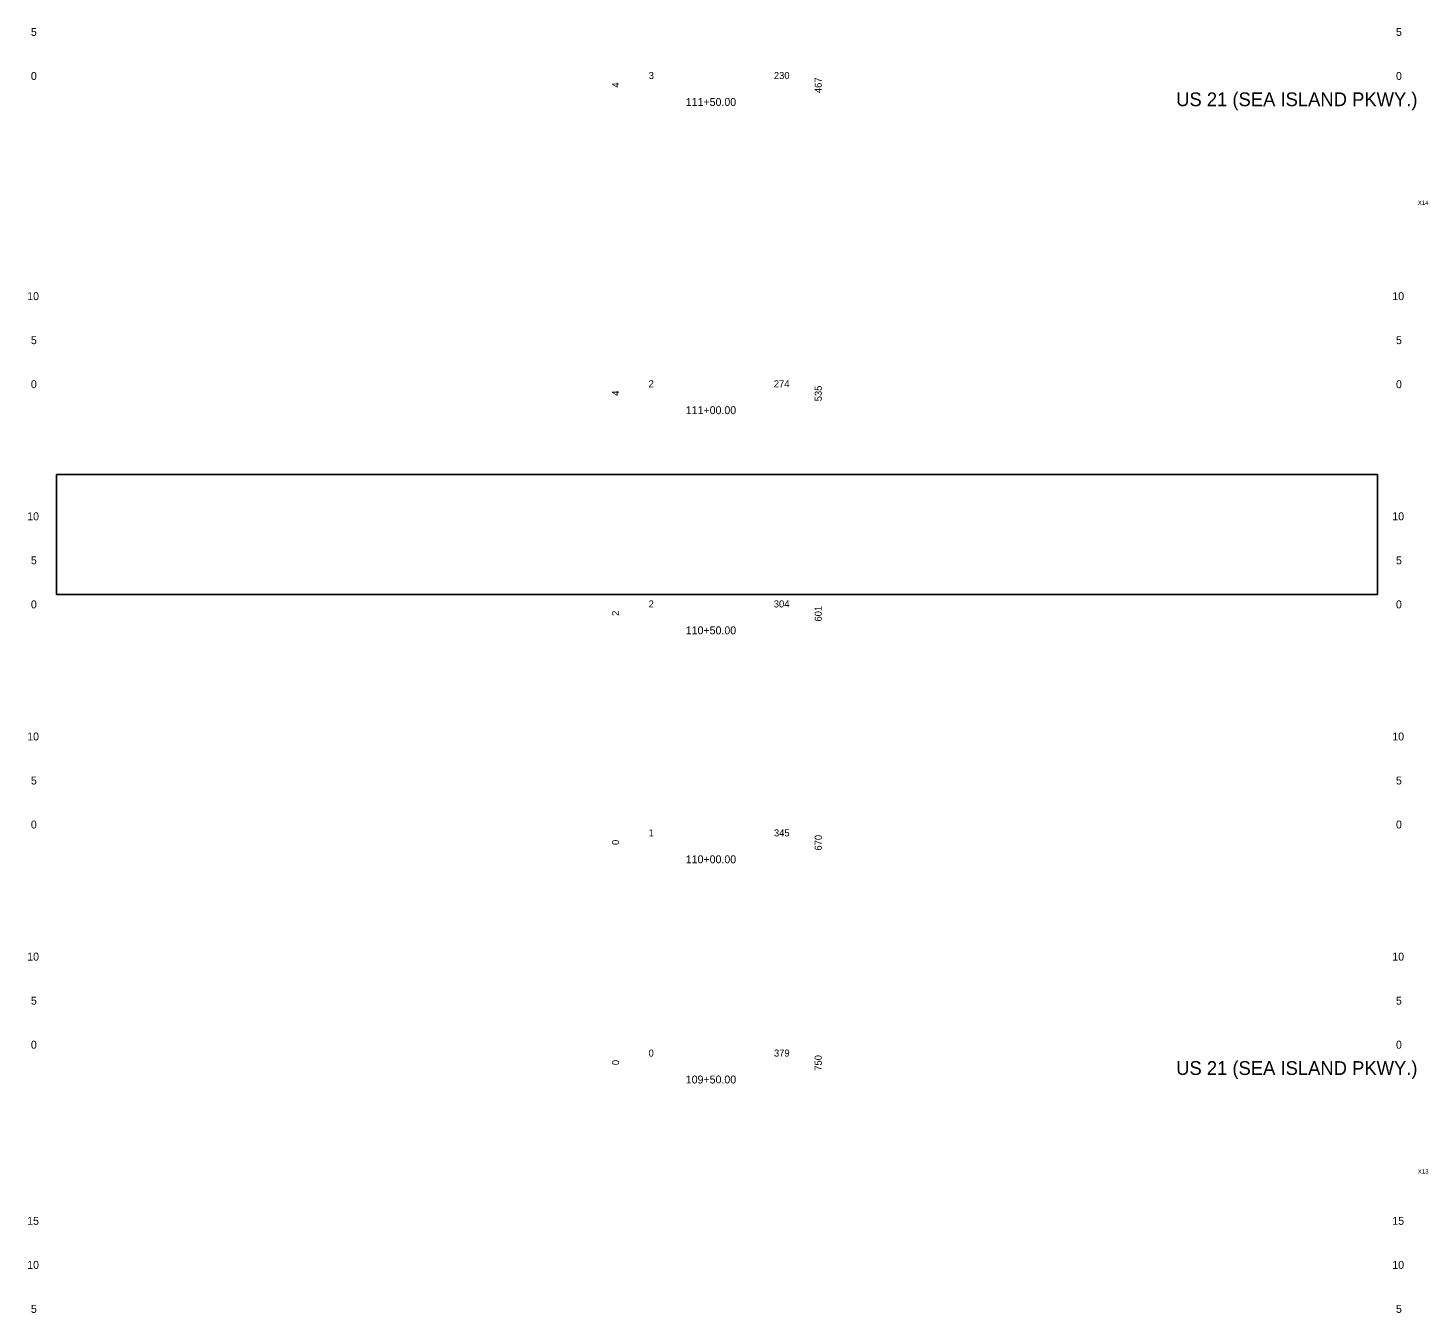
# Model space of a CAD drawing. Extents: x 971 to 1131, y 2203 to 6043.
# Drawn here: x 971.5 to 1130.5, y 5146.9 to 5292.8 of the extents above; entities that cross this region are included whole.
import ezdxf

# ---------------------------------------------------------------- set-up
doc = ezdxf.new("R2010")
doc.units = 0
for name, color, linetype in [('RD_SHT_Misc1', 7, 'Continuous'), ('RD_SHT_ShtClip', 7, 'Continuous'), ('RD_SHT_TX', 7, 'Continuous'), ('RD_XS_TX_Station', 7, 'Continuous')]:
    doc.layers.add(name, color=color, linetype=linetype)

msp = doc.modelspace()

# ---------------------------------------------------------------- linework, layer by layer
at = {"layer": 'RD_SHT_ShtClip'}
msp.add_lwpolyline([(974.73, 5242.07), (1124.73, 5242.07), (1124.73, 5228.46), (974.73, 5228.46)], close=True, dxfattribs=at)

# ---------------------------------------------------------------- texts
at = {"layer": 'RD_SHT_Misc1'}
for s, p in [('3', (1041.99, 5286.97)), ('230', (1056.2, 5286.97)), ('2', (1041.98, 5251.97)), ('274', (1056.19, 5251.97)), ('2', (1041.98, 5226.97)), ('304', (1056.19, 5226.97)), ('1', (1041.98, 5200.97)), ('345', (1056.21, 5200.97)), ('0', (1041.97, 5175.97)), ('379', (1056.21, 5175.97))]:
    msp.add_text(s, height=0.8, dxfattribs=at).set_placement(p)
for s, p in [('4', (1038.63, 5286)), ('467', (1061.64, 5285.37)), ('4', (1038.63, 5251)), ('535', (1061.64, 5250.38)), ('601', (1061.64, 5225.37)), ('2', (1038.63, 5226.01)), ('0', (1038.63, 5200)), ('670', (1061.64, 5199.36)), ('750', (1061.64, 5174.36)), ('0', (1038.63, 5175))]:
    msp.add_text(s, height=0.8, rotation=90, dxfattribs=at).set_placement(p)
at = {"layer": 'RD_SHT_TX'}
for s, height, p in [('5', 0.9, (971.84, 5291.87)), ('5', 0.9, (1126.84, 5291.87)), ('0', 0.9, (971.84, 5286.87)), ('0', 0.9, (1126.84, 5286.87)), ('US 21 (SEA ISLAND PKWY.)', 1.5625, (1101.88, 5283.89)), ('10', 0.9, (971.42, 5261.87)), ('10', 0.9, (1126.42, 5261.87)), ('5', 0.9, (971.84, 5256.87)), ('5', 0.9, (1126.84, 5256.87)), ('0', 0.9, (971.84, 5251.87)), ('0', 0.9, (1126.84, 5251.87)), ('10', 0.9, (971.42, 5236.87)), ('10', 0.9, (1126.42, 5236.87)), ('5', 0.9, (971.84, 5231.87)), ('5', 0.9, (1126.84, 5231.87)), ('0', 0.9, (971.84, 5226.87)), ('0', 0.9, (1126.84, 5226.87)), ('10', 0.9, (971.42, 5211.87)), ('10', 0.9, (1126.42, 5211.87)), ('5', 0.9, (971.84, 5206.87)), ('5', 0.9, (1126.84, 5206.87)), ('0', 0.9, (971.84, 5201.87)), ('0', 0.9, (1126.84, 5201.87)), ('10', 0.9, (971.42, 5186.87)), ('10', 0.9, (1126.42, 5186.87)), ('5', 0.9, (971.84, 5181.87)), ('5', 0.9, (1126.84, 5181.87)), ('0', 0.9, (971.84, 5176.87)), ('0', 0.9, (1126.84, 5176.87)), ('US 21 (SEA ISLAND PKWY.)', 1.5625, (1101.88, 5173.89)), ('15', 0.9, (971.42, 5156.87)), ('15', 0.9, (1126.42, 5156.87)), ('10', 0.9, (971.42, 5151.87)), ('10', 0.9, (1126.42, 5151.87)), ('5', 0.9, (971.84, 5146.87)), ('5', 0.9, (1126.84, 5146.87))]:
    msp.add_text(s, height=height, dxfattribs=at).set_placement(p)
for s, p in [('X14', (1129.31, 5272.68)), ('X13', (1129.31, 5162.68))]:
    msp.add_text(s, height=0.5, rotation=360, dxfattribs=at).set_placement(p)
at = {"layer": 'RD_XS_TX_Station'}
for s, p in [('111+50.00', (1046.2, 5283.92)), ('111+00.00', (1046.2, 5248.92)), ('110+50.00', (1046.2, 5223.92)), ('110+00.00', (1046.2, 5197.92)), ('109+50.00', (1046.2, 5172.92))]:
    msp.add_text(s, height=0.9, dxfattribs=at).set_placement(p)

doc.saveas('drawing.dxf')
